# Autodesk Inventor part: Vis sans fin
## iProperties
Created: 2011-07
Part Number: Vis sans fin
Material: Steel, Mild
Document SubType Name: Modeling
Designer: Laur
Density: 7.86 g/cm^3
CustomPartVersion: 1
Author: Laur
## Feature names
1. Corps de base [Extrusion]
2. Chamfer1
3. Chamfer2
4. Dent
5. Motif de la dent [Circular Pattern]
6. Dent gauche
7. Motif de dent gauche [Circular Pattern]
